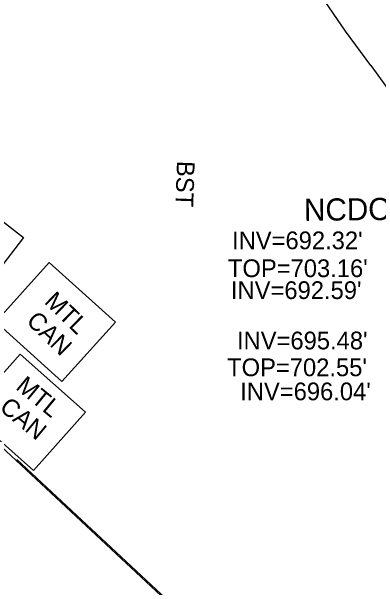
# Model space of a CAD drawing. Extents: x 1516784 to 1522736, y 634838 to 639369.
# Drawn here: x 1520280.1 to 1520362.8, y 637671.2 to 637801.1 of the extents above; entities that cross this region are included whole.
import ezdxf

# ---------------------------------------------------------------- set-up
doc = ezdxf.new("R2010")
doc.units = 0
for name, color, linetype in [('Exist Building', 7, 'Continuous'), ('Exist Building Metal Canopy', 7, 'Continuous'), ('Exist Building Text', 7, 'Continuous'), ('Exist Environmental Wetland Boundary Cogo Elevation', 7, 'Continuous'), ('Exist Environmental Wetland Boundary Cogo Number', 7, 'Continuous'), ('Exist Roads EOP Other Text', 7, 'Continuous'), ('Exist Utilities Power UG Cable SUE LOS B Text', 7, 'Continuous'), ('Exist Utilities Sanitary Sewer Manhole Text', 7, 'Continuous'), ('Exist Utilities Sanitary Sewer UG Line Invert Elevation', 7, 'Continuous'), ('Scratch_Level_5', 7, 'Continuous')]:
    doc.layers.add(name, color=color, linetype=linetype)

msp = doc.modelspace()

# ---------------------------------------------------------------- linework, layer by layer
at = {"layer": 'Exist Building'}
msp.add_lwpolyline([(1520282.78, 637750.1), (1520277.08, 637742.69), (1520270.92, 637747.43), (1520276.62, 637754.84)], close=True, dxfattribs=at)
at = {"layer": 'Exist Building Metal Canopy'}
for points in [[(1520288.56, 637744.46), (1520303.52, 637730.98), (1520291.45, 637717.58), (1520276.48, 637731.06)], [(1520282.04, 637723.79), (1520296.74, 637710.7), (1520285.02, 637697.55), (1520270.33, 637710.64)], [(1520267.56, 637712.41), (1520367.88, 637618.75), (1520346.25, 637595.26), (1520289.08, 637648.53), (1520281.68, 637641.04), (1520254.16, 637667.17)]]:
    msp.add_lwpolyline(points, close=True, dxfattribs=at)
at = {"layer": 'Exist Environmental Wetland Boundary Cogo Elevation'}
msp.add_lwpolyline([(1520363.45, 637614.7), (1520367.65, 637619.39), (1520281.28, 637700.02)], dxfattribs=at)
at = {"layer": 'Exist Environmental Wetland Boundary Cogo Number'}
msp.add_line((1520361.05, 637788.84), (1520367.62, 637779.75), dxfattribs=at)
msp.add_lwpolyline([(1520361.05, 637788.84), (1520355.35, 637796.64), (1520350.77, 637803.31), (1520345.38, 637811.48), (1520336.33, 637825.41), (1520331.64, 637833.12), (1520326.35, 637842.52), (1520320.42, 637853.22), (1520316.84, 637859.32), (1520316.25, 637859.78)], dxfattribs=at)

# ---------------------------------------------------------------- texts
at = {"layer": 'Exist Building Text'}
for s, rotation, p in [('MTL', 315.7861, (1520287.26, 637735.4)), ('CAN', 315.7861, (1520283.19, 637730.99)), ('MTL', 320.4904, (1520280.83, 637716.06)), ('CAN', 320.4904, (1520277.13, 637711.33))]:
    msp.add_text(s, height=4, rotation=rotation, dxfattribs=at).set_placement(p)
at = {"layer": 'Exist Roads EOP Other Text'}
msp.add_text('BST', height=4, rotation=267.9794, dxfattribs=at).set_placement((1520317.37, 637767.41))
at = {"layer": 'Exist Utilities Power UG Cable SUE LOS B Text'}
msp.add_text('NCDOT Pole', height=5, rotation=0.6235, dxfattribs=at).set_placement((1520346, 637753.83))
at = {"layer": 'Exist Utilities Sanitary Sewer Manhole Text'}
for s, p in [("TOP=703.16'", (1520328.84, 637741.15)), ("TOP=702.55'", (1520328.66, 637718.81))]:
    msp.add_text(s, height=4, dxfattribs=at).set_placement(p)
at = {"layer": 'Exist Utilities Sanitary Sewer UG Line Invert Elevation'}
for s, p in [("INV=692.32'", (1520329.77, 637747.44)), ("INV=692.59'", (1520329.52, 637736.21)), ("INV=695.48'", (1520330.88, 637724.86)), ("INV=696.04'", (1520331.61, 637713.38))]:
    msp.add_text(s, height=4, dxfattribs=at).set_placement(p)
at = {"layer": 'Scratch_Level_5'}
msp.add_text('COLUMN LOCATION', height=500, rotation=335.0373, dxfattribs=at).set_placement((1516680.97, 637558.94))

doc.saveas('drawing.dxf')
